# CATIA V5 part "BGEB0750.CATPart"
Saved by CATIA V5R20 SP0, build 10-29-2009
Part number: BGEB0750
Revision: 7
Definition: design
Nomenclature: BGEB0750
Source: made
Description: NOT SPECIFIED
Bounding box of the stored display mesh (mm): x -18.123 to 18.123, y -18.123 to 18.123, z -12.7 to 25.4
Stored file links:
  C:\Users\Utente\Desktop\3D files BGEB\BGEB0750.CATPart
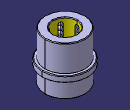
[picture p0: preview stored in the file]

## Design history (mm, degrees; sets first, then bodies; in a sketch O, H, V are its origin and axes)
Body1 "MANIFOLD_SOLID_BREP #38" (main body)
  Solid1: solid without history
Body2 "MANIFOLD_SOLID_BREP #76"
  Solid2: solid without history
Body3 "MANIFOLD_SOLID_BREP #114"
  Solid3: solid without history
Body4 "MANIFOLD_SOLID_BREP #152"
  Solid4: solid without history
Body5 "MANIFOLD_SOLID_BREP #190"
  Solid5: solid without history
Body6 "MANIFOLD_SOLID_BREP #228"
  Solid6: solid without history
Body7 "MANIFOLD_SOLID_BREP #266"
  Solid7: solid without history
Body8 "MANIFOLD_SOLID_BREP #304"
  Solid8: solid without history
Body9 "MANIFOLD_SOLID_BREP #2006"
  Solid9: solid without history
Body10 "MANIFOLD_SOLID_BREP #2044"
  Solid10: solid without history
Body11 "MANIFOLD_SOLID_BREP #2082"
  Solid11: solid without history
Body12 "MANIFOLD_SOLID_BREP #2120"
  Solid12: solid without history
Body13 "MANIFOLD_SOLID_BREP #2158"
  Solid13: solid without history
Body14 "MANIFOLD_SOLID_BREP #2196"
  Solid14: solid without history
Body15 "MANIFOLD_SOLID_BREP #2234"
  Solid15: solid without history
Body16 "MANIFOLD_SOLID_BREP #2272"
  Solid16: solid without history
Body17 "MANIFOLD_SOLID_BREP #2310"
  Solid17: solid without history
Body18 "MANIFOLD_SOLID_BREP #2348"
  Solid18: solid without history
Body19 "MANIFOLD_SOLID_BREP #2386"
  Solid19: solid without history
Body20 "MANIFOLD_SOLID_BREP #2424"
  Solid20: solid without history
Body21 "MANIFOLD_SOLID_BREP #2462"
  Solid21: solid without history
Body22 "MANIFOLD_SOLID_BREP #2500"
  Solid22: solid without history
Body23 "MANIFOLD_SOLID_BREP #2538"
  Solid23: solid without history
Body24 "MANIFOLD_SOLID_BREP #2576"
  Solid24: solid without history
Body25 "MANIFOLD_SOLID_BREP #2614"
  Solid25: solid without history
Body26 "MANIFOLD_SOLID_BREP #2652"
  Solid26: solid without history
Body27 "MANIFOLD_SOLID_BREP #2690"
  Solid27: solid without history
Body28 "MANIFOLD_SOLID_BREP #2728"
  Solid28: solid without history
Body29 "MANIFOLD_SOLID_BREP #2766"
  Solid29: solid without history
Body30 "MANIFOLD_SOLID_BREP #2804"
  Solid30: solid without history
Body31 "MANIFOLD_SOLID_BREP #2842"
  Solid31: solid without history
Body32 "MANIFOLD_SOLID_BREP #2880"
  Solid32: solid without history
Body33 "MANIFOLD_SOLID_BREP #2918"
  Solid33: solid without history
Body34 "MANIFOLD_SOLID_BREP #2956"
  Solid34: solid without history
Body35 "MANIFOLD_SOLID_BREP #2994"
  Solid35: solid without history
Body36 "MANIFOLD_SOLID_BREP #3032"
  Solid36: solid without history
Body37 "MANIFOLD_SOLID_BREP #3070"
  Solid37: solid without history
Body38 "MANIFOLD_SOLID_BREP #3108"
  Solid38: solid without history
Body39 "MANIFOLD_SOLID_BREP #3146"
  Solid39: solid without history
Body40 "MANIFOLD_SOLID_BREP #3184"
  Solid40: solid without history
Body41 "MANIFOLD_SOLID_BREP #3222"
  Solid41: solid without history
Body42 "MANIFOLD_SOLID_BREP #3260"
  Solid42: solid without history
Body43 "MANIFOLD_SOLID_BREP #3298"
  Solid43: solid without history
Body44 "MANIFOLD_SOLID_BREP #3336"
  Solid44: solid without history
Body45 "MANIFOLD_SOLID_BREP #3374"
  Solid45: solid without history
Body46 "MANIFOLD_SOLID_BREP #3412"
  Solid46: solid without history
Body47 "MANIFOLD_SOLID_BREP #3450"
  Solid47: solid without history
Body48 "MANIFOLD_SOLID_BREP #3488"
  Solid48: solid without history
Body49 "MANIFOLD_SOLID_BREP #3526"
  Solid49: solid without history
Body50 "MANIFOLD_SOLID_BREP #3564"
  Solid50: solid without history
Body51 "MANIFOLD_SOLID_BREP #3602"
  Solid51: solid without history
Body52 "MANIFOLD_SOLID_BREP #3640"
  Solid52: solid without history
Body53 "MANIFOLD_SOLID_BREP #3678"
  Solid53: solid without history
Body54 "MANIFOLD_SOLID_BREP #3716"
  Solid54: solid without history
Body55 "MANIFOLD_SOLID_BREP #3754"
  Solid55: solid without history
Body56 "MANIFOLD_SOLID_BREP #3792"
  Solid56: solid without history
Body57 "MANIFOLD_SOLID_BREP #3830"
  Solid57: solid without history
Body58 "MANIFOLD_SOLID_BREP #3868"
  Solid58: solid without history
Body59 "MANIFOLD_SOLID_BREP #3906"
  Solid59: solid without history
Body60 "MANIFOLD_SOLID_BREP #3944"
  Solid60: solid without history
Body61 "MANIFOLD_SOLID_BREP #3982"
  Solid61: solid without history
